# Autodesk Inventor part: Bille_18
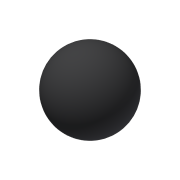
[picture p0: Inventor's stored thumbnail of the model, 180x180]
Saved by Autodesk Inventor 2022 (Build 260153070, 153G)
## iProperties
Created: 2018-06
Part Number: Bille_18
Material: Acier
Document SubType Name: Modeling
Designer: Fabian Perrée
Density: 7.85 g/cm^3
Appearance: Plaque
Mass: 23.971 g
Surface Area: 10.1788 cm^2
Volume: 3.05363 cm^3
Author: Fabian Perrée
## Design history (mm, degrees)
sketch "Esquisse1"
  geometry: L1 (0, 9)-(0, -9); A1 r 9 centre (0, 0) between (0, -9) and (0, 9); 2 further points
  constraints: 2 coincident, 2 end point, 2 point on circle, 1 centre point, 1 midpoint, 1 vertical
  dimensions: "d2" = 9 radius of A1
revolve "Révolution1" sketch "Esquisse1" stored, may be unused: angle "d3" = 90 deg
node "Solide1"
